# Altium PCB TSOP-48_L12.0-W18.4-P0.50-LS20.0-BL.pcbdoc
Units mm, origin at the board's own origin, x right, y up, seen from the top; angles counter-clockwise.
Board outline 25.29 x 34.09 mm, 2 copper layers (Top Layer, Bottom Layer), stack 0 mm thick; 1 components, 0 nets, 48 pads, 0 vias.
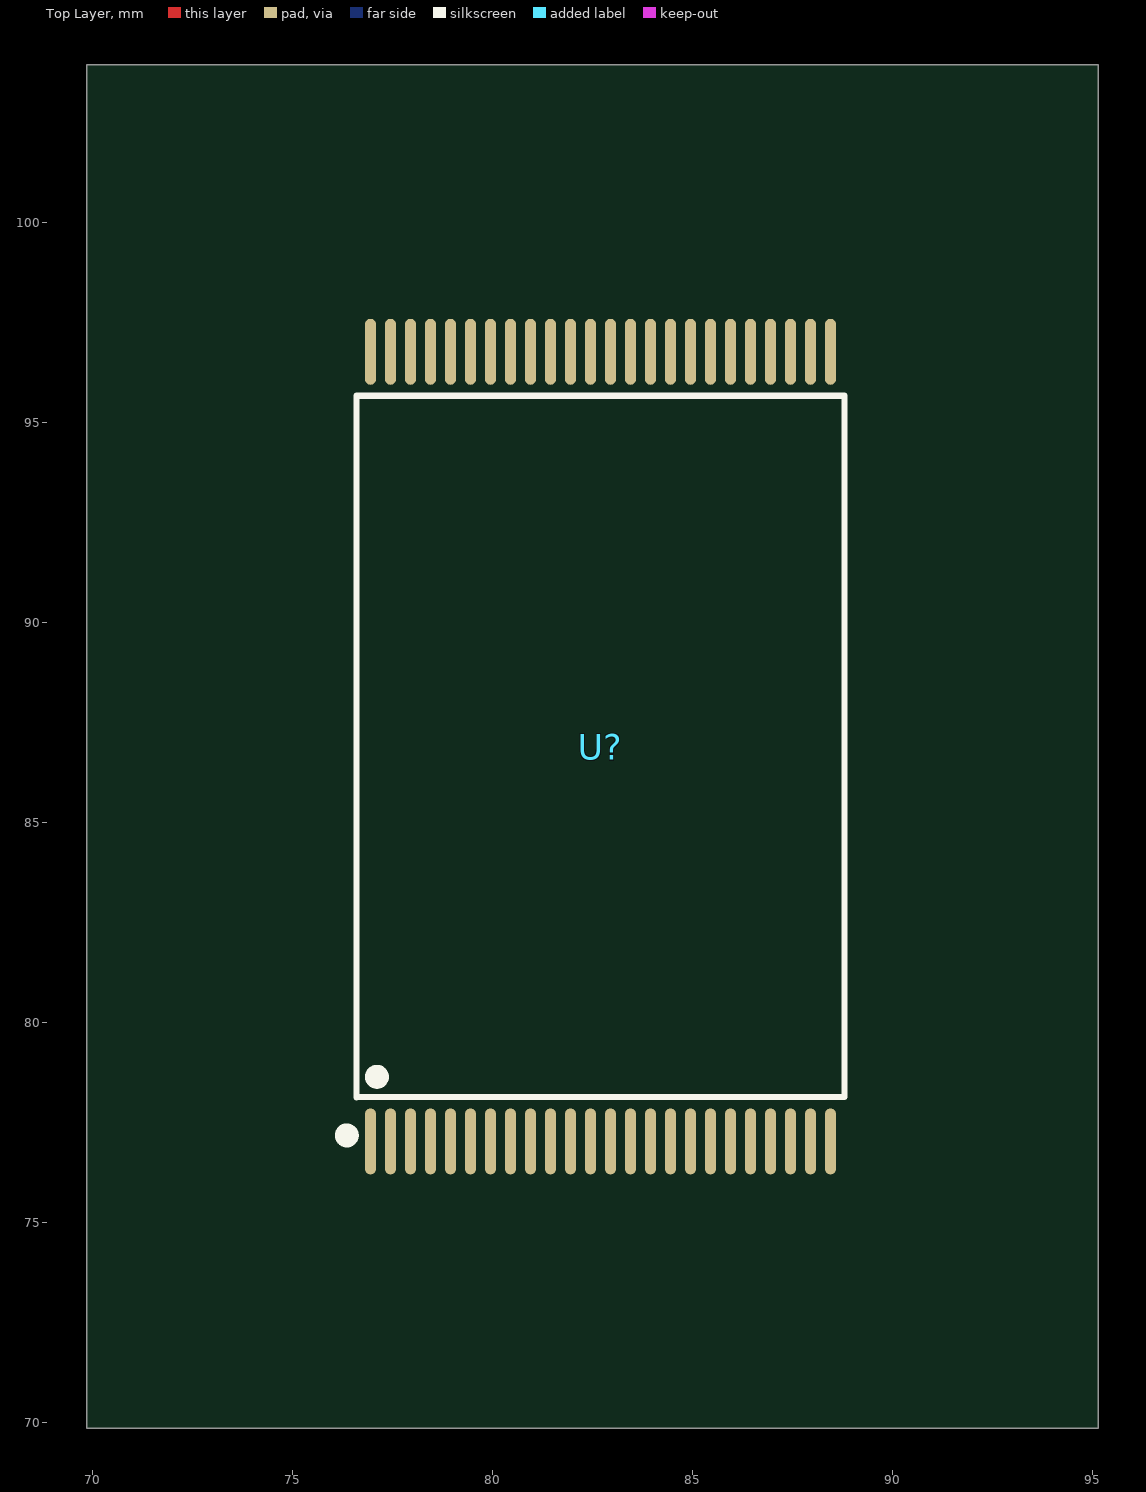
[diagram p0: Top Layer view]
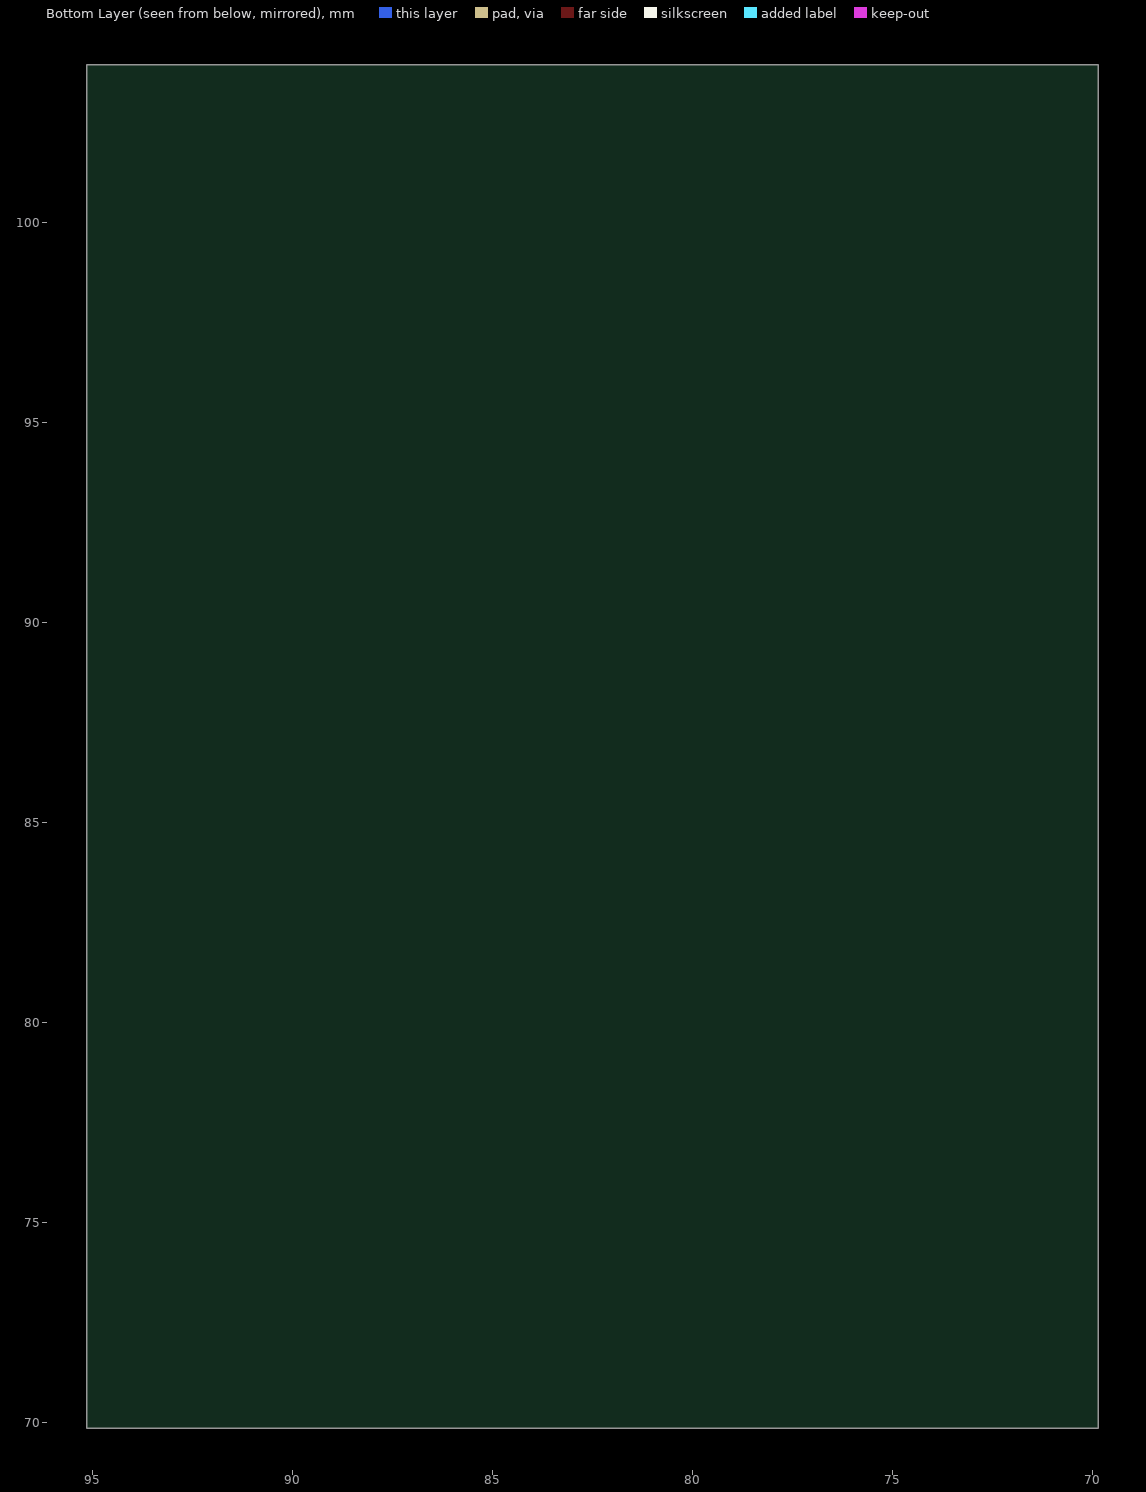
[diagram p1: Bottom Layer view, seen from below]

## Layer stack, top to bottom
Top Layer: signal copper (thickness not stored)
Bottom Layer: signal copper (thickness not stored)

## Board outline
95.138,69.85 69.85,69.85 69.85,103.94 95.138,103.94

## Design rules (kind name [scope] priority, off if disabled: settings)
PasteMaskExpansion "Paste Mask Expansion" [All] p1: expansion=0
SolderMaskExpansion "Solder Mask Expansion" [IsVia] p1: expansion=-25.4 istentingtop=TRUE
SolderMaskExpansion "Solder Mask Expansion" [All] p2: expansion=0.051 istentingtop=FALSE

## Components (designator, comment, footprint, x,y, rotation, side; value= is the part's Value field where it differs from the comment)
U? "" TSOP-48_L12.0-W18.4-P0.50-LS20.0-BL 82.692,86.895 r0 top

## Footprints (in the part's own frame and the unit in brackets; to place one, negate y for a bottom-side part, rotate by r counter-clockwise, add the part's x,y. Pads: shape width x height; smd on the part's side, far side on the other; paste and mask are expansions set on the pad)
TSOP-48_L12.0-W18.4-P0.50-LS20.0-BL [mm]
  oval 0.28x1.65 smd: 1(-5.75,-9.87) 2(-5.25,-9.87) 3(-4.75,-9.87) 4(-4.25,-9.87) 5(-3.75,-9.87) 6(-3.25,-9.87) 7(-2.75,-9.87) 8(-2.25,-9.87) 9(-1.75,-9.87) 10(-1.25,-9.87) 11(-0.75,-9.87) 12(-0.25,-9.87) 13(0.25,-9.87) 14(0.75,-9.87) 15(1.25,-9.87) 16(1.75,-9.87) 17(2.25,-9.87) 18(2.75,-9.87) 19(3.25,-9.87) 20(3.75,-9.87) 21(4.25,-9.87) 22(4.75,-9.87) 23(5.25,-9.87) 24(5.75,-9.87) 25(5.75,9.87) 26(5.25,9.87) 27(4.75,9.87) 28(4.25,9.87) 29(3.75,9.87) 30(3.25,9.87) 31(2.75,9.87) 32(2.25,9.87) 33(1.75,9.87) 34(1.25,9.87) 35(0.75,9.87) 36(0.25,9.87) 37(-0.25,9.87) 38(-0.75,9.87) 39(-1.25,9.87) 40(-1.75,9.87) 41(-2.25,9.87) 42(-2.75,9.87) 43(-3.25,9.87) 44(-3.75,9.87) 45(-4.25,9.87) 46(-4.75,9.87) 47(-5.25,9.87) 48(-5.75,9.87)
  silkscreen extent -6.49,-9.87 6.1,8.77

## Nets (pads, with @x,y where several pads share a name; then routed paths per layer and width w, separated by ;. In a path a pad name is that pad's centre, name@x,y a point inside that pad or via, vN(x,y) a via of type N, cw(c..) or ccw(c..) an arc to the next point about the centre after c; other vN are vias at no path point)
pads on no net: U?.1 U?.2 U?.3 U?.4 U?.5 U?.6 U?.7 U?.8 U?.9 U?.10 U?.11 U?.12 U?.13 U?.14 U?.15 U?.16 U?.17 U?.18 U?.19 U?.20 U?.21 U?.22 U?.23 U?.24 U?.25 U?.26 U?.27 U?.28 U?.29 U?.30 U?.31 U?.32 U?.33 U?.34 U?.35 U?.36 U?.37 U?.38 U?.39 U?.40 U?.41 U?.42 U?.43 U?.44 U?.45 U?.46 U?.47 U?.48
